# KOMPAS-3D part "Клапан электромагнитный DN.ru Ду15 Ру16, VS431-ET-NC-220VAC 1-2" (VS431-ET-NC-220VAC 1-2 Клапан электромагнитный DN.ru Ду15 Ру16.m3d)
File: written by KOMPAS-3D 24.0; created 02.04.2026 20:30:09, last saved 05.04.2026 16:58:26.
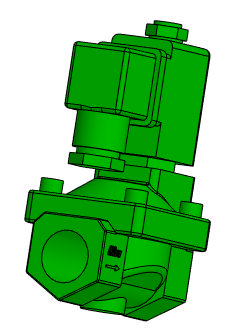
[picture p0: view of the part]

Document properties: Автор: artio; Полное имя файла: C:\Users\artio\OneDrive\Рабочий стол\Клапан электромагнитный DN.ru\VS431\VS431-ET-NC\VS431-ET-NC-220VAC\Ду15\VS431-ET-NC-220VAC 1-2 Клапан электромагнитный DN.ru Ду15 Ру16.m3d

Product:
- Body: Тело 1  | qty 1
    Масса: 1.030062
- Part/product: Клапан электромагнитный DN.ru Ду15 Ру16  | designation VS431-ET-NC-220VAC 1-2
    Масса: 0.732
    Раздел спецификации: Прочие изделия
    Примечание: D130-04705
    additional columns: ef56311e-7521-43dc-8291-0e6108b3d81d; VS400-ET-NC-220VAC 1-2; artio; c; Шероховатость не задана; Да

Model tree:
1. Операция без истории:1

Expressions: VS431-ET-NC-220VAC 1-2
